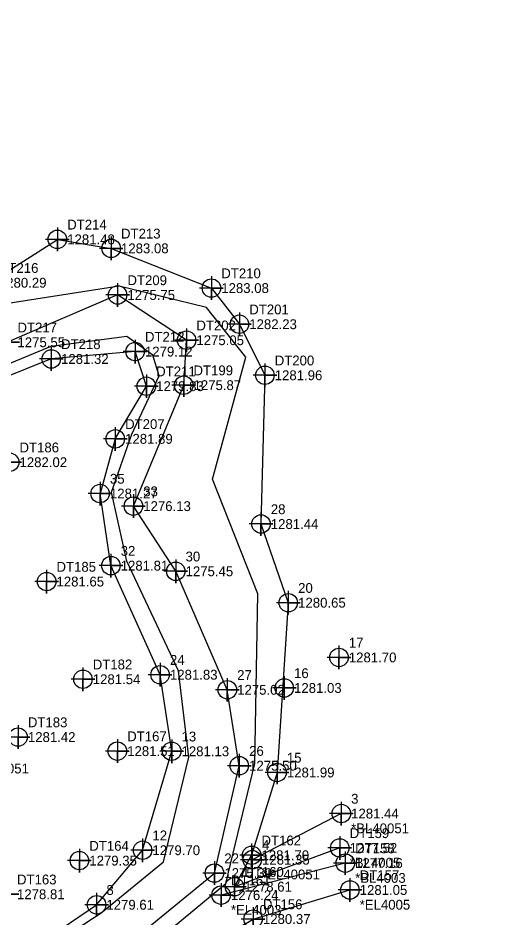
# Model space of a CAD drawing. Extents: x 1394009 to 1394411, y 957864 to 958364.
# Drawn here: x 1394217.7 to 1394338.6, y 958114.8 to 958343.4 of the extents above; entities that cross this region are included whole.
import ezdxf

# ---------------------------------------------------------------- set-up
doc = ezdxf.new("R2010")
doc.units = 0
for name, color, linetype in [('Exist DTM Breakline', 7, 'Continuous'), ('Exist DTM Breakline Cogo Comment', 7, 'Continuous'), ('Exist DTM Breakline Cogo Elevation', 7, 'Continuous'), ('Exist DTM Breakline Cogo Number', 7, 'Continuous'), ('Exist DTM Breakline Cogo Point CELL', 7, 'Continuous'), ('Exist DTM Breakline Underwater', 7, 'Continuous'), ('Exist DTM Breakline Underwater Cogo Elevation', 7, 'Continuous'), ('Exist DTM Breakline Underwater Cogo Number', 7, 'Continuous'), ('Exist DTM Breakline Underwater Cogo Point CELL', 7, 'Continuous'), ('Exist DTM Drainline', 7, 'Continuous'), ('Exist DTM Drainline Cogo Comment', 7, 'Continuous'), ('Exist DTM Drainline Cogo Elevation', 7, 'Continuous'), ('Exist DTM Drainline Cogo Number', 7, 'Continuous'), ('Exist DTM Drainline Cogo Point CELL', 7, 'Continuous'), ('Exist DTM Regular Point Cogo Elevation', 7, 'Continuous'), ('Exist Hydro Stream or Body of Water', 7, 'Continuous'), ('PH Exist DTM NCFMP LIDAR Elevation Point', 7, 'Continuous'), ('Raster_Level_0', 7, 'Continuous')]:
    doc.layers.add(name, color=color, linetype=linetype)

msp = doc.modelspace()

# ---------------------------------------------------------------- linework, layer by layer
at = {"layer": 'Exist DTM Breakline'}
msp.add_line((1394299.8088, 958141.2846), (1394277.2043, 958129.5633), dxfattribs=at)
for points in [[(1394242.4363, 958236.4587), (1394250.3213, 958249.8392), (1394247.4683, 958258.6227), (1394226.1736, 958256.7484), (1394200.4578, 958246.4971), (1394175.9465, 958237.5482), (1394166.0162, 958243.1539), (1394150.9651, 958262.3435), (1394145.9876, 958283.4911), (1394149.6991, 958293.4183), (1394147.595, 958317.4165), (1394162.2974, 958343.3573)], [(1394183.7059, 958302.6672), (1394175.5913, 958290.3266), (1394176.7902, 958272.6343), (1394192.7029, 958271.0839), (1394210.3962, 958276.1116), (1394227.7375, 958287.1282), (1394241.3942, 958284.8435), (1394266.8472, 958274.7526), (1394273.951, 958265.5798), (1394280.4133, 958252.6154), (1394279.4205, 958214.8325), (1394286.3541, 958194.8367), (1394283.5006, 958151.7161)], [(1394242.4363, 958236.4587), (1394238.5837, 958222.5694)], [(1394220.2003, 958106.2482), (1394237.6839, 958118.114), (1394249.3757, 958131.9705), (1394256.7573, 958157.1006), (1394253.8139, 958176.5432), (1394241.3147, 958204.2553), (1394238.5837, 958222.5694)], [(1394283.5006, 958151.7161), (1394277.0519, 958130.6921)], [(1394299.4345, 958132.5594), (1394272.6812, 958122.7076), (1394277.0519, 958130.6921)], [(1394338.5703, 958071.7873), (1394311.6428, 958061.939), (1394296.3165, 958058.5038), (1394278.7037, 958060.8799), (1394270.8162, 958064.205), (1394260.0757, 958069.6149), (1394248.6938, 958087.5642), (1394243.8244, 958095.3933), (1394260.8199, 958104.7758), (1394277.4189, 958114.4853), (1394301.9851, 958121.8746)]]:
    msp.add_lwpolyline(points, dxfattribs=at)
at = {"layer": 'Exist DTM Breakline Cogo Point CELL'}
for points in [[(1394227.7375, 958290.1282), (1394227.7375, 958284.1282), (1394227.7375, 958287.1282), (1394230.7375, 958287.1282), (1394224.7375, 958287.1282)], [(1394241.3942, 958287.8435), (1394241.3942, 958281.8435), (1394241.3942, 958284.8435), (1394244.3942, 958284.8435), (1394238.3942, 958284.8435)], [(1394266.8472, 958277.7526), (1394266.8472, 958271.7526), (1394266.8472, 958274.7526), (1394269.8472, 958274.7526), (1394263.8472, 958274.7526)], [(1394273.951, 958268.5798), (1394273.951, 958262.5798), (1394273.951, 958265.5798), (1394276.951, 958265.5798), (1394270.951, 958265.5798)], [(1394226.1736, 958259.7484), (1394226.1736, 958253.7484), (1394226.1736, 958256.7484), (1394229.1736, 958256.7484), (1394223.1736, 958256.7484)], [(1394247.4683, 958261.6227), (1394247.4683, 958255.6227), (1394247.4683, 958258.6227), (1394250.4683, 958258.6227), (1394244.4683, 958258.6227)], [(1394280.4133, 958255.6154), (1394280.4133, 958249.6154), (1394280.4133, 958252.6154), (1394283.4133, 958252.6154), (1394277.4133, 958252.6154)], [(1394250.3213, 958252.8392), (1394250.3213, 958246.8392), (1394250.3213, 958249.8392), (1394253.3213, 958249.8392), (1394247.3213, 958249.8392)], [(1394242.4363, 958239.4587), (1394242.4363, 958233.4587), (1394242.4363, 958236.4587), (1394245.4363, 958236.4587), (1394239.4363, 958236.4587)], [(1394238.5837, 958225.5694), (1394238.5837, 958219.5694), (1394238.5837, 958222.5694), (1394241.5837, 958222.5694), (1394235.5837, 958222.5694)], [(1394279.4205, 958217.8325), (1394279.4205, 958211.8325), (1394279.4205, 958214.8325), (1394282.4205, 958214.8325), (1394276.4205, 958214.8325)], [(1394241.3147, 958207.2553), (1394241.3147, 958201.2553), (1394241.3147, 958204.2553), (1394244.3147, 958204.2553), (1394238.3147, 958204.2553)], [(1394286.3541, 958197.8367), (1394286.3541, 958191.8367), (1394286.3541, 958194.8367), (1394289.3541, 958194.8367), (1394283.3541, 958194.8367)], [(1394253.8139, 958179.5432), (1394253.8139, 958173.5432), (1394253.8139, 958176.5432), (1394256.8139, 958176.5432), (1394250.8139, 958176.5432)], [(1394285.3198, 958176.1857), (1394285.3198, 958170.1857), (1394285.3198, 958173.1857), (1394288.3198, 958173.1857), (1394282.3198, 958173.1857)], [(1394256.7573, 958160.1006), (1394256.7573, 958154.1006), (1394256.7573, 958157.1006), (1394259.7573, 958157.1006), (1394253.7573, 958157.1006)], [(1394283.5006, 958154.7161), (1394283.5006, 958148.7161), (1394283.5006, 958151.7161), (1394286.5006, 958151.7161), (1394280.5006, 958151.7161)], [(1394299.8088, 958144.2846), (1394299.8088, 958138.2846), (1394299.8088, 958141.2846), (1394302.8088, 958141.2846), (1394296.8088, 958141.2846)], [(1394249.3757, 958134.9705), (1394249.3757, 958128.9705), (1394249.3757, 958131.9705), (1394252.3757, 958131.9705), (1394246.3757, 958131.9705)], [(1394277.0519, 958133.6921), (1394277.0519, 958127.6921), (1394277.0519, 958130.6921), (1394280.0519, 958130.6921), (1394274.0519, 958130.6921)], [(1394299.4345, 958135.5594), (1394299.4345, 958129.5594), (1394299.4345, 958132.5594), (1394302.4345, 958132.5594), (1394296.4345, 958132.5594)], [(1394277.2043, 958132.5633), (1394277.2043, 958126.5633), (1394277.2043, 958129.5633), (1394280.2043, 958129.5633), (1394274.2043, 958129.5633)], [(1394272.6812, 958125.7076), (1394272.6812, 958119.7076), (1394272.6812, 958122.7076), (1394275.6812, 958122.7076), (1394269.6812, 958122.7076)], [(1394301.9851, 958124.8746), (1394301.9851, 958118.8746), (1394301.9851, 958121.8746), (1394304.9851, 958121.8746), (1394298.9851, 958121.8746)], [(1394237.6839, 958121.114), (1394237.6839, 958115.114), (1394237.6839, 958118.114), (1394240.6839, 958118.114), (1394234.6839, 958118.114)], [(1394277.4189, 958117.4853), (1394277.4189, 958111.4853), (1394277.4189, 958114.4853), (1394280.4189, 958114.4853), (1394274.4189, 958114.4853)]]:
    msp.add_lwpolyline(points, dxfattribs=at)
for centre in [(1394227.7375, 958287.1282), (1394241.3942, 958284.8435), (1394266.8472, 958274.7526), (1394273.951, 958265.5798), (1394247.4683, 958258.6227), (1394226.1736, 958256.7484), (1394280.4133, 958252.6154), (1394250.3213, 958249.8392), (1394242.4363, 958236.4587), (1394238.5837, 958222.5694), (1394279.4205, 958214.8325), (1394241.3147, 958204.2553), (1394286.3541, 958194.8367), (1394253.8139, 958176.5432), (1394285.3198, 958173.1857), (1394256.7573, 958157.1006), (1394283.5006, 958151.7161), (1394299.8088, 958141.2846), (1394249.3757, 958131.9705), (1394299.4345, 958132.5594), (1394277.0519, 958130.6921), (1394277.2043, 958129.5633), (1394272.6812, 958122.7076), (1394301.9851, 958121.8746), (1394237.6839, 958118.114), (1394277.4189, 958114.4853)]:
    msp.add_circle(centre, 2.344, dxfattribs=at)
at = {"layer": 'Exist DTM Breakline Underwater'}
msp.add_lwpolyline([(1394229.3063, 958094.7507), (1394267.6222, 958126.159), (1394273.9153, 958153.4417), (1394270.8807, 958172.7151), (1394257.7841, 958202.8194), (1394247.0365, 958219.368), (1394259.7999, 958250.0935), (1394260.5275, 958261.5147), (1394243.0302, 958273.0023), (1394215.1121, 958260.9873), (1394175.4465, 958249.379), (1394164.3967, 958267.5944), (1394161.8631, 958300.0699), (1394178.2103, 958310.6665)], dxfattribs=at)
at = {"layer": 'Exist DTM Breakline Underwater Cogo Point CELL'}
for points in [[(1394243.0302, 958276.0023), (1394243.0302, 958270.0023), (1394243.0302, 958273.0023), (1394246.0302, 958273.0023), (1394240.0302, 958273.0023)], [(1394215.1121, 958263.9873), (1394215.1121, 958257.9873), (1394215.1121, 958260.9873), (1394218.1121, 958260.9873), (1394212.1121, 958260.9873)], [(1394260.5275, 958264.5147), (1394260.5275, 958258.5147), (1394260.5275, 958261.5147), (1394263.5275, 958261.5147), (1394257.5275, 958261.5147)], [(1394259.7999, 958253.0935), (1394259.7999, 958247.0935), (1394259.7999, 958250.0935), (1394262.7999, 958250.0935), (1394256.7999, 958250.0935)], [(1394247.0365, 958222.368), (1394247.0365, 958216.368), (1394247.0365, 958219.368), (1394250.0365, 958219.368), (1394244.0365, 958219.368)], [(1394257.7841, 958205.8194), (1394257.7841, 958199.8194), (1394257.7841, 958202.8194), (1394260.7841, 958202.8194), (1394254.7841, 958202.8194)], [(1394270.8807, 958175.7151), (1394270.8807, 958169.7151), (1394270.8807, 958172.7151), (1394273.8807, 958172.7151), (1394267.8807, 958172.7151)], [(1394273.9153, 958156.4417), (1394273.9153, 958150.4417), (1394273.9153, 958153.4417), (1394276.9153, 958153.4417), (1394270.9153, 958153.4417)], [(1394267.6222, 958129.159), (1394267.6222, 958123.159), (1394267.6222, 958126.159), (1394270.6222, 958126.159), (1394264.6222, 958126.159)]]:
    msp.add_lwpolyline(points, dxfattribs=at)
for centre in [(1394243.0302, 958273.0023), (1394260.5275, 958261.5147), (1394259.7999, 958250.0935), (1394247.0365, 958219.368), (1394257.7841, 958202.8194), (1394270.8807, 958172.7151), (1394273.9153, 958153.4417), (1394267.6222, 958126.159)]:
    msp.add_circle(centre, 2.344, dxfattribs=at)
at = {"layer": 'Exist DTM Drainline'}
msp.add_line((1394300.8283, 958128.6881), (1394269.2993, 958120.561), dxfattribs=at)
at = {"layer": 'Exist DTM Drainline Cogo Point CELL'}
for points in [[(1394300.8283, 958131.6881), (1394300.8283, 958125.6881), (1394300.8283, 958128.6881), (1394303.8283, 958128.6881), (1394297.8283, 958128.6881)], [(1394269.2993, 958123.561), (1394269.2993, 958117.561), (1394269.2993, 958120.561), (1394272.2993, 958120.561), (1394266.2993, 958120.561)]]:
    msp.add_lwpolyline(points, dxfattribs=at)
for centre in [(1394300.8283, 958128.6881), (1394269.2993, 958120.561)]:
    msp.add_circle(centre, 2.344, dxfattribs=at)
at = {"layer": 'Exist Hydro Stream or Body of Water'}
for points in [[(1394221.231, 958104.5797), (1394238.8971, 958116.0346), (1394254.7004, 958129.0614), (1394261.0998, 958155.6228), (1394258.5223, 958177.5159), (1394245.4045, 958205.4301), (1394241.5211, 958222.9502), (1394246.6022, 958237.6666), (1394253.5489, 958252.431), (1394251.9663, 958257.7082), (1394245.398, 958262.4184), (1394226.1093, 958259.8812), (1394198.4822, 958248.5108), (1394177.4215, 958243.2011), (1394168.9777, 958246.0581), (1394155.8669, 958264.1507), (1394149.2709, 958283.1502), (1394154.661, 958297.4554), (1394160.3871, 958316.4078), (1394173.556, 958323.8378)], [(1394231.5705, 958091.2594), (1394270.5171, 958123.5077), (1394277.8383, 958154.0025), (1394278.608, 958197.1243), (1394267.0972, 958226.2539), (1394275.5986, 958257.1902), (1394265.6306, 958269.8313), (1394243.4303, 958275.2121), (1394210.2309, 958270.0539), (1394177.5999, 958260.6264), (1394172.1027, 958270.6648), (1394169.7578, 958290.7959), (1394182.6519, 958307.5361)]]:
    msp.add_lwpolyline(points, dxfattribs=at)
at = {"layer": 'PH Exist DTM NCFMP LIDAR Elevation Point'}
for points in [[(1394215.6264, 958233.5223), (1394215.6264, 958227.5223), (1394215.6264, 958230.5223), (1394218.6264, 958230.5223), (1394212.6264, 958230.5223)], [(1394225.0157, 958203.209), (1394225.0157, 958197.209), (1394225.0157, 958200.209), (1394228.0157, 958200.209), (1394222.0157, 958200.209)], [(1394299.225, 958183.9382), (1394299.225, 958177.9382), (1394299.225, 958180.9382), (1394302.225, 958180.9382), (1394296.225, 958180.9382)], [(1394234.2246, 958178.3998), (1394234.2246, 958172.3998), (1394234.2246, 958175.3998), (1394237.2246, 958175.3998), (1394231.2246, 958175.3998)], [(1394217.7585, 958163.7088), (1394217.7585, 958157.7088), (1394217.7585, 958160.7088), (1394220.7585, 958160.7088), (1394214.7585, 958160.7088)], [(1394242.9644, 958160.1459), (1394242.9644, 958154.1459), (1394242.9644, 958157.1459), (1394245.9644, 958157.1459), (1394239.9644, 958157.1459)], [(1394233.343, 958132.332), (1394233.343, 958126.332), (1394233.343, 958129.332), (1394236.343, 958129.332), (1394230.343, 958129.332)], [(1394214.9941, 958123.785), (1394214.9941, 958117.785), (1394214.9941, 958120.785), (1394217.9941, 958120.785), (1394211.9941, 958120.785)]]:
    msp.add_lwpolyline(points, dxfattribs=at)
for centre in [(1394215.6264, 958230.5223), (1394225.0157, 958200.209), (1394299.225, 958180.9382), (1394234.2246, 958175.3998), (1394217.7585, 958160.7088), (1394242.9644, 958157.1459), (1394233.343, 958129.332)]:
    msp.add_circle(centre, 2.344, dxfattribs=at)

# ---------------------------------------------------------------- texts
at = {"layer": 'Exist DTM Breakline Cogo Comment'}
for s, p in [('*BL40051', (1394205.8254, 958151.4773)), ('*BL40051', (1394302.3088, 958136.2846)), ('*BL4005', (1394301.9345, 958127.5594)), ('*EL40051', (1394279.7043, 958124.5633)), ('*EL4005', (1394304.4851, 958116.8746))]:
    msp.add_text(s, height=2.5, dxfattribs=at).set_placement(p)
at = {"layer": 'Exist DTM Breakline Cogo Elevation'}
for s, p in [('1281.48', (1394230.2375, 958285.8782)), ('1283.08', (1394243.8942, 958283.5935)), ('1280.29', (1394212.8962, 958274.8616)), ('1283.08', (1394269.3472, 958273.5026)), ('1282.23', (1394276.451, 958264.3298)), ('1279.12', (1394249.9683, 958257.3727)), ('1281.32', (1394228.6736, 958255.4984)), ('1281.96', (1394282.9133, 958251.3654)), ('1279.83', (1394252.8213, 958248.5892)), ('1281.89', (1394244.9363, 958235.2087)), ('1281.27', (1394241.0837, 958221.3194)), ('1281.44', (1394281.9205, 958213.5825)), ('1281.81', (1394243.8147, 958203.0053)), ('1280.65', (1394288.8541, 958193.5867)), ('1281.83', (1394256.3139, 958175.2932)), ('1281.03', (1394287.8198, 958171.9357)), ('1281.13', (1394259.2573, 958155.8506)), ('1281.99', (1394286.0006, 958150.4661)), ('1281.44', (1394302.3088, 958140.0346)), ('1277.52', (1394301.9345, 958131.3094)), ('1279.70', (1394251.8757, 958130.7205)), ('1281.70', (1394279.5519, 958129.4421)), ('1281.35', (1394279.7043, 958128.3133)), ('1278.61', (1394275.1812, 958121.4576)), ('1281.05', (1394304.4851, 958120.6246)), ('1279.61', (1394240.1839, 958116.864)), ('1280.37', (1394279.9189, 958113.2353))]:
    msp.add_text(s, height=2.5, dxfattribs=at).set_placement(p)
at = {"layer": 'Exist DTM Breakline Cogo Number'}
for s, p in [('DT214', (1394230.2375, 958289.6282)), ('DT213', (1394243.8942, 958287.3435)), ('DT216', (1394212.8962, 958278.6116)), ('DT210', (1394269.3472, 958277.2526)), ('DT201', (1394276.451, 958268.0798)), ('DT218', (1394228.6736, 958259.2484)), ('DT212', (1394249.9683, 958261.1227)), ('DT200', (1394282.9133, 958255.1154)), ('DT211', (1394252.8213, 958252.3392)), ('DT207', (1394244.9363, 958238.9587)), ('35', (1394241.0837, 958225.0694)), ('28', (1394281.9205, 958217.3325)), ('32', (1394243.8147, 958206.7553)), ('20', (1394288.8541, 958197.3367)), ('24', (1394256.3139, 958179.0432)), ('16', (1394287.8198, 958175.6857)), ('13', (1394259.2573, 958159.6006)), ('15', (1394286.0006, 958154.2161)), ('3', (1394302.3088, 958143.7846)), ('12', (1394251.8757, 958134.4705)), ('DT159', (1394301.9345, 958135.0594)), ('4', (1394279.7043, 958132.0633)), ('DT162', (1394279.5519, 958133.1921)), ('DT160', (1394275.1812, 958125.2076)), ('DT157', (1394304.4851, 958124.3746)), ('8', (1394240.1839, 958120.614)), ('DT156', (1394279.9189, 958116.9853))]:
    msp.add_text(s, height=2.5, dxfattribs=at).set_placement(p)
at = {"layer": 'Exist DTM Breakline Underwater Cogo Elevation'}
for s, p in [('1275.75', (1394245.5302, 958271.7523)), ('1275.55', (1394217.6121, 958259.7373)), ('1275.05', (1394263.0275, 958260.2647)), ('1275.87', (1394262.2999, 958248.8435)), ('1276.13', (1394249.5365, 958218.118)), ('1275.45', (1394260.2841, 958201.5694)), ('1275.02', (1394273.3807, 958171.4651)), ('1275.50', (1394276.4153, 958152.1917)), ('1275.39', (1394270.1222, 958124.909))]:
    msp.add_text(s, height=2.5, dxfattribs=at).set_placement(p)
at = {"layer": 'Exist DTM Breakline Underwater Cogo Number'}
for s, p in [('DT209', (1394245.5302, 958275.5023)), ('DT202', (1394263.0275, 958264.0147)), ('DT217', (1394217.6121, 958263.4873)), ('DT199', (1394262.2999, 958252.5935)), ('33', (1394249.5365, 958221.868)), ('30', (1394260.2841, 958205.3194)), ('27', (1394273.3807, 958175.2151)), ('26', (1394276.4153, 958155.9417)), ('22', (1394270.1222, 958128.659))]:
    msp.add_text(s, height=2.5, dxfattribs=at).set_placement(p)
at = {"layer": 'Exist DTM Drainline Cogo Comment'}
for s, p in [('*BL4003', (1394303.3283, 958123.6881)), ('*EL4003', (1394271.7993, 958115.561))]:
    msp.add_text(s, height=2.5, dxfattribs=at).set_placement(p)
at = {"layer": 'Exist DTM Drainline Cogo Elevation'}
for s, p in [('1277.16', (1394303.3283, 958127.4381)), ('1276.24', (1394271.7993, 958119.311))]:
    msp.add_text(s, height=2.5, dxfattribs=at).set_placement(p)
at = {"layer": 'Exist DTM Drainline Cogo Number'}
for s, p in [('DT158', (1394303.3283, 958131.1881)), ('DT161', (1394271.7993, 958123.061))]:
    msp.add_text(s, height=2.5, dxfattribs=at).set_placement(p)
at = {"layer": 'Exist DTM Regular Point Cogo Elevation'}
for s, p in [('1282.02', (1394218.1264, 958229.2723)), ('1281.65', (1394227.5157, 958198.959)), ('1281.70', (1394301.725, 958179.6882)), ('1281.54', (1394236.7246, 958174.1498)), ('1281.42', (1394220.2585, 958159.4588)), ('1281.51', (1394245.4644, 958155.8959)), ('1279.35', (1394235.843, 958128.082)), ('1278.81', (1394217.4941, 958119.535))]:
    msp.add_text(s, height=2.5, dxfattribs=at).set_placement(p)
at = {"layer": 'Raster_Level_0'}
for s, p in [('DT186', (1394218.1264, 958233.0223)), ('DT185', (1394227.5157, 958202.709)), ('17', (1394301.725, 958183.4382)), ('DT182', (1394236.7246, 958177.8998)), ('DT183', (1394220.2585, 958163.2088)), ('DT167', (1394245.4644, 958159.6459)), ('DT164', (1394235.843, 958131.832)), ('DT163', (1394217.4941, 958123.285))]:
    msp.add_text(s, height=2.5, dxfattribs=at).set_placement(p)

doc.saveas('drawing.dxf')
